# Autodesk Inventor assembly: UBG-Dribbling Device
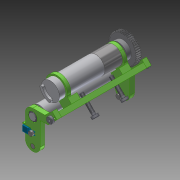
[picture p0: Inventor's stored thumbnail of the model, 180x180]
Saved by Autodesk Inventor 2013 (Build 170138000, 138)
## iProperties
Created: 2012-07
Part Number: UBG-Dribbling Device
Document SubType Name: Assembly
Designer: rYan
Mass: 134.795 g
Surface Area: 248.793 cm^2
Volume: 34.8082 cm^3
Density: 3.8725 g/cm^3
Author: rYan
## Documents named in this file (20)
- D:\SVN\2013\Inventor\Dribbling Device\UBG-Dribbling Device.iam
- D:\SVN\2013\Inventor\Dribbling Device\DribblerstrebeA.ipt
- D:\SVN\2013\Inventor\Dribbling Device\Daempfersteg.ipt
- D:\SVN\2013\Inventor\Dribbling Device\DribblerstrebeB.ipt
- D:\SVN\2013\Inventor\Dribbling Device\MG-Maxon EC16 mit Getriebe.iam
- D:\SVN\2013\Inventor\Dribbling Device\Dribblingmotorhalter hinten.ipt
- D:\SVN\2013\Inventor\Dribbling Device\Dribblingmotorhalter.ipt
- D:\SVN\2013\Inventor\Inhaltscenter\de-DE\ISO 8752(2)\ISO 8752 - 4,5 x 8  (2) DIN EN ISO.ipt
- D:\SVN\2013\Inventor\Kaufteile\GFM_0608_04.ipt
- D:\SVN\2013\Inventor\Kaufteile\Zahnrad z48.ipt
- D:\SVN\2013\Inventor\Dribbling Device\MG-Dribblingwelle.iam
- D:\SVN\2013\Inventor\Inhaltscenter\de-DE\DIN 7984\DIN 7984 - M3 x 8.ipt
- D:\SVN\2013\Inventor\Kaufteile\IR LED TSKS5400.ipt
- D:\SVN\2013\Inventor\Kaufteile\Photodiode BPV22NF.ipt
- D:\SVN\2013\Inventor\Inhaltscenter\de-DE\ISO 4762(1)\ISO 4762 - M2 x 4DIN EN ISO.ipt
- D:\SVN\2013\Inventor\Inhaltscenter\de-DE\DIN ISO 8734(1)\ISO 8734 - 2 x 6 - ADIN EN.ipt
- D:\SVN\2013\Inventor\Inhaltscenter\en-US\DIN 7984\DIN 7984 - M3 x 6.ipt
- D:\SVN\2013\Inventor\Inhaltscenter\en-US\DIN 7984\DIN 7984 - M3 x 16.ipt
- D:\SVN\2013\Inventor\Inhaltscenter\en-US\DIN ISO 8734(1)\ISO 8734 - 2 x 6 - ADIN EN.ipt
- D:\SVN\2013\Inventor\Inhaltscenter\en-US\ISO 2338(1)\ISO 2338 - 4 m6 x 8DIN EN.ipt
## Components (33 placed, 18 different names)
1. DribblerstrebeA:1 — Passend:1, Passend:11, Passend:12, Passend:14, Passend:47, Fluchtend:9, Passend:48, Passend:51, Mate:58, Winkel:1, Passend:59, Winkel:2
2. Dämpfersteg:1 — Passend:1, Passend:2, Passend:4, Passend:9, Passend:40, Passend:41, Passend:42, Passend:43, Passend:44, Passend:45, Passend:46, Passend:47, Fluchtend:8, Fluchtend:9, Passend:52, Passend:53, Passend:54, Passend:55, Passend:66, Passend:67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
3. DribblerstrebeB:1 — Passend:2, Passend:13, Passend:15, Passend:46, Fluchtend:8, Passend:49, Passend:50, Mate:60, Passend:61, Winkel:3
4. Dribblingmotorhalter hinten:1 — Passend:8, Passend:9, Passend:41, Passend:70, Passend:71
5. Dribblingmotorhalter:1 — Passend:3, Passend:4, Passend:5, Passend:6, Passend:7, Passend:40, Passend:72, Passend:73, Passend:83
6. MG-Maxon EC16 mit Getriebe:1 [sub-assembly] — Passend:3, Passend:5, Passend:6, Passend:7, Passend:8, Passend:10, Fluchtend:6
7. DIN EN ISO 8752 4,5 x 8:1 — Passend:10, Fluchtend:6, Passend:17
8. GFM_0608_04:1 — Passend:13, Passend:15
9. GFM_0608_04:2 — Passend:12, Passend:14, Passend:16
10. MG-Dribblingwelle:1 [sub-assembly] — Passend:11, Passend:16, Fluchtend:7
11. Zahnrad z=48:1 — Passend:17, Fluchtend:7
12. DIN EN ISO 2338 4 m6 x 8:1
13. DIN EN ISO 2338 4 m6 x 8:2
14. DIN 7984 M3 x 8:1 — Passend:49, Passend:50
15. DIN 7984 M3 x 8:2 — Passend:48, Passend:51
16. DIN 7984 M3 x 6:1 — Passend:43, Passend:45
17. DIN 7984 M3 x 6:2 — Passend:42, Passend:44
18. DIN 7984 M3 x 16:1 — Passend:52, Passend:53
19. DIN 7984 M3 x 16:2 — Passend:54, Passend:55
20. IR LED TSKS5400:1 — Mate:60, Passend:61, Winkel:3, Passend:63
21. Photodiode BPV22NF:1 — Mate:58, Winkel:1, Passend:59, Winkel:2, Passend:65
22. DIN EN ISO 4762 M2 x 4:1 — Passend:63
23. DIN EN ISO 4762 M2 x 4:2 — Passend:65
24. DIN EN ISO 8734 2 x 6 - A:1 — Passend:66, Passend:70
25. DIN EN ISO 8734 2 x 6 - A:2 — Passend:67, Passend:71
26. DIN EN ISO 8734 2 x 6 - A:3 — Passend:68, Passend:72
27. DIN EN ISO 8734 2 x 6 - A:4 — Passend:69, Passend:73
28. DIN EN ISO 8734 2 x 6 - A:5 — Passend:77, Passend:80
29. DIN EN ISO 8734 2 x 6 - A:6 — Passend:76, Passend:81
30. DIN EN ISO 8734 2 x 6 - A:7 — Passend:75, Passend:79
31. DIN EN ISO 8734 2 x 6 - A:8 — Passend:74, Passend:78
32. DIN EN ISO 4762 M2 x 4:3 — Passend:83
33. DIN EN ISO 4762 M2 x 4:4
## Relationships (63: Mate 56, Flush 4, Angle 3)
- Passend:1 [Mate]: DribblerstrebeA:1 ↔ Dämpfersteg:1
- Passend:2 [Mate]: Dämpfersteg:1 ↔ DribblerstrebeB:1
- Passend:3 [Mate]: Dribblingmotorhalter:1 ↔ MG-Maxon EC16 mit Getriebe:1
- Passend:4 [Mate]: Dämpfersteg:1 ↔ Dribblingmotorhalter:1
- Passend:5 [Mate]: Dribblingmotorhalter:1 ↔ MG-Maxon EC16 mit Getriebe:1
- Passend:6 [Mate]: Dribblingmotorhalter:1 ↔ MG-Maxon EC16 mit Getriebe:1
- Passend:7 [Mate]: Dribblingmotorhalter:1 ↔ MG-Maxon EC16 mit Getriebe:1
- Passend:8 [Mate]: Dribblingmotorhalter hinten:1 ↔ MG-Maxon EC16 mit Getriebe:1
- Passend:9 [Mate]: Dämpfersteg:1 ↔ Dribblingmotorhalter hinten:1
- Passend:10 [Mate]: MG-Maxon EC16 mit Getriebe:1 ↔ DIN EN ISO 8752 4,5 x 8:1
- Fluchtend:6 [Flush]: MG-Maxon EC16 mit Getriebe:1 ↔ DIN EN ISO 8752 4,5 x 8:1
- Passend:11 [Mate]: DribblerstrebeA:1 ↔ MG-Dribblingwelle:1
- Passend:12 [Mate]: DribblerstrebeA:1 ↔ GFM_0608_04:2
- Passend:13 [Mate]: DribblerstrebeB:1 ↔ GFM_0608_04:1
- Passend:14 [Mate]: DribblerstrebeA:1 ↔ GFM_0608_04:2
- Passend:15 [Mate]: DribblerstrebeB:1 ↔ GFM_0608_04:1
- Passend:16 [Mate]: GFM_0608_04:2 ↔ MG-Dribblingwelle:1
- Passend:17 [Mate]: DIN EN ISO 8752 4,5 x 8:1 ↔ Zahnrad z=48:1
- Fluchtend:7 [Flush]: MG-Dribblingwelle:1 ↔ Zahnrad z=48:1
- Passend:40 [Mate]: Dämpfersteg:1 ↔ Dribblingmotorhalter:1
- Passend:41 [Mate]: Dämpfersteg:1 ↔ Dribblingmotorhalter hinten:1
- Passend:42 [Mate]: Dämpfersteg:1 ↔ DIN 7984 M3 x 6:2
- Passend:43 [Mate]: Dämpfersteg:1 ↔ DIN 7984 M3 x 6:1
- Passend:44 [Mate]: Dämpfersteg:1 ↔ DIN 7984 M3 x 6:2
- Passend:45 [Mate]: Dämpfersteg:1 ↔ DIN 7984 M3 x 6:1
- Passend:46 [Mate]: Dämpfersteg:1 ↔ DribblerstrebeB:1
- Passend:47 [Mate]: DribblerstrebeA:1 ↔ Dämpfersteg:1
- Fluchtend:8 [Flush]: Dämpfersteg:1 ↔ DribblerstrebeB:1
- Fluchtend:9 [Flush]: DribblerstrebeA:1 ↔ Dämpfersteg:1
- Passend:48 [Mate]: DribblerstrebeA:1 ↔ DIN 7984 M3 x 8:2
- Passend:49 [Mate]: DribblerstrebeB:1 ↔ DIN 7984 M3 x 8:1
- Passend:50 [Mate]: DribblerstrebeB:1 ↔ DIN 7984 M3 x 8:1
- Passend:51 [Mate]: DribblerstrebeA:1 ↔ DIN 7984 M3 x 8:2
- Passend:52 [Mate]: Dämpfersteg:1 ↔ DIN 7984 M3 x 16:1
- Passend:53 [Mate]: Dämpfersteg:1 ↔ DIN 7984 M3 x 16:1
- Passend:54 [Mate]: Dämpfersteg:1 ↔ DIN 7984 M3 x 16:2
- Passend:55 [Mate]: Dämpfersteg:1 ↔ DIN 7984 M3 x 16:2
- Mate:58: DribblerstrebeA:1 ↔ Photodiode BPV22NF:1
- Winkel:1 [Angle]: DribblerstrebeA:1 ↔ Photodiode BPV22NF:1
- Passend:59 [Mate]: DribblerstrebeA:1 ↔ Photodiode BPV22NF:1
- Winkel:2 [Angle]: DribblerstrebeA:1 ↔ Photodiode BPV22NF:1
- Mate:60: DribblerstrebeB:1 ↔ IR LED TSKS5400:1
- Passend:61 [Mate]: DribblerstrebeB:1 ↔ IR LED TSKS5400:1
- Winkel:3 [Angle]: DribblerstrebeB:1 ↔ IR LED TSKS5400:1
- Passend:63 [Mate]: IR LED TSKS5400:1 ↔ DIN EN ISO 4762 M2 x 4:1
- Passend:65 [Mate]: Photodiode BPV22NF:1 ↔ DIN EN ISO 4762 M2 x 4:2
- Passend:66 [Mate]: Dämpfersteg:1 ↔ DIN EN ISO 8734 2 x 6 - A:1
- Passend:67 [Mate]: Dämpfersteg:1 ↔ DIN EN ISO 8734 2 x 6 - A:2
- Passend:68 [Mate]: Dämpfersteg:1 ↔ DIN EN ISO 8734 2 x 6 - A:3
- Passend:69 [Mate]: Dämpfersteg:1 ↔ DIN EN ISO 8734 2 x 6 - A:4
- Passend:70 [Mate]: Dribblingmotorhalter hinten:1 ↔ DIN EN ISO 8734 2 x 6 - A:1
- Passend:71 [Mate]: Dribblingmotorhalter hinten:1 ↔ DIN EN ISO 8734 2 x 6 - A:2
- Passend:72 [Mate]: Dribblingmotorhalter:1 ↔ DIN EN ISO 8734 2 x 6 - A:3
- Passend:73 [Mate]: Dribblingmotorhalter:1 ↔ DIN EN ISO 8734 2 x 6 - A:4
- Passend:74 [Mate]: Dämpfersteg:1 ↔ DIN EN ISO 8734 2 x 6 - A:8
- Passend:75 [Mate]: Dämpfersteg:1 ↔ DIN EN ISO 8734 2 x 6 - A:7
- Passend:76 [Mate]: Dämpfersteg:1 ↔ DIN EN ISO 8734 2 x 6 - A:6
- Passend:77 [Mate]: Dämpfersteg:1 ↔ DIN EN ISO 8734 2 x 6 - A:5
- Passend:78 [Mate]: Dämpfersteg:1 ↔ DIN EN ISO 8734 2 x 6 - A:8
- Passend:79 [Mate]: Dämpfersteg:1 ↔ DIN EN ISO 8734 2 x 6 - A:7
- Passend:80 [Mate]: Dämpfersteg:1 ↔ DIN EN ISO 8734 2 x 6 - A:5
- Passend:81 [Mate]: Dämpfersteg:1 ↔ DIN EN ISO 8734 2 x 6 - A:6
- Passend:83 [Mate]: Dribblingmotorhalter:1 ↔ DIN EN ISO 4762 M2 x 4:3
